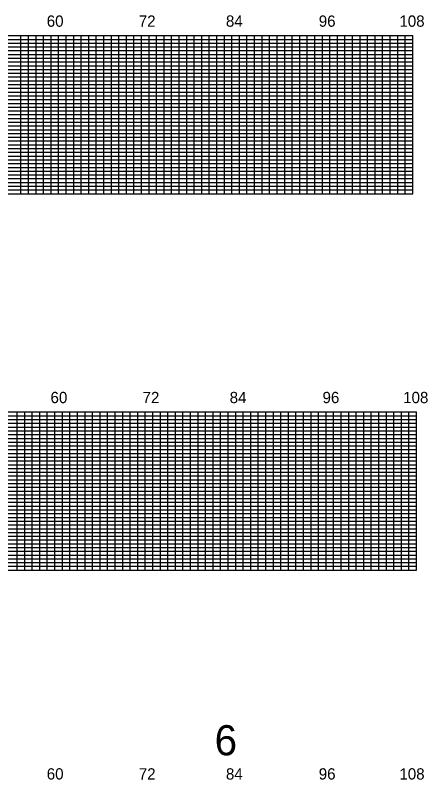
# Model space of a CAD drawing. Extents: x 1950433 to 1956806, y 750939 to 777666.
# Drawn here: x 1954069 to 1956806, y 764572 to 769649 of the extents above; entities that cross this region are included whole.
import ezdxf

# ---------------------------------------------------------------- set-up
doc = ezdxf.new("R2010")
doc.units = 0
doc.layers.add('RD_PD_WallFill', color=7, linetype='Continuous')
doc.layers.add('RD_Sketch8', color=7, linetype='Continuous')

msp = doc.modelspace()

# ---------------------------------------------------------------- linework, layer by layer
at = {"layer": 'RD_PD_WallFill'}
for p, q in [((1951356.4, 769514.1), (1956706.4, 769514.2)), ((1954106.4, 768464.2), (1954106.4, 769514.2)), ((1954156.4, 768464.2), (1954156.4, 769514.2)), ((1954206.4, 768464.2), (1954206.4, 769514.2)), ((1954256.4, 768464.2), (1954256.4, 769514.2)), ((1954306.4, 768464.2), (1954306.4, 769514.2)), ((1954356.4, 768464.2), (1954356.4, 769514.2)), ((1954406.4, 768464.2), (1954406.4, 769514.2)), ((1954456.4, 768464.1), (1954456.4, 769514.2)), ((1954506.4, 768464.2), (1954506.4, 769514.2)), ((1954556.4, 768464.2), (1954556.4, 769514.2)), ((1954606.4, 768464.2), (1954606.4, 769514.2)), ((1954656.4, 768464.2), (1954656.4, 769514.2)), ((1954706.4, 768464.2), (1954706.4, 769514.2)), ((1954756.4, 768464.1), (1954756.4, 769514.2)), ((1954806.4, 768464.1), (1954806.4, 769514.2)), ((1954856.4, 768464.2), (1954856.4, 769514.2)), ((1954906.4, 768464.2), (1954906.4, 769514.2)), ((1954956.4, 768464.2), (1954956.4, 769514.2)), ((1955006.4, 768464.2), (1955006.4, 769514.2)), ((1955056.4, 768464.2), (1955056.4, 769514.2)), ((1955106.4, 768464.2), (1955106.4, 769514.2)), ((1955156.4, 768464.2), (1955156.4, 769514.2)), ((1955206.4, 768464.2), (1955206.4, 769514.2)), ((1955256.4, 768464.2), (1955256.4, 769514.2)), ((1955306.4, 768464.2), (1955306.4, 769514.2)), ((1955356.4, 768464.2), (1955356.4, 769514.2)), ((1955406.4, 768464.2), (1955406.4, 769514.2)), ((1955456.4, 768464.2), (1955456.4, 769514.2)), ((1955506.4, 768464.2), (1955506.4, 769514.2)), ((1955556.4, 768464.2), (1955556.4, 769514.2)), ((1955606.4, 768464.2), (1955606.4, 769514.2)), ((1955656.4, 768464.2), (1955656.4, 769514.2)), ((1955706.4, 768464.2), (1955706.4, 769514.2)), ((1955756.4, 768464.2), (1955756.4, 769514.2)), ((1955806.4, 768464.2), (1955806.4, 769514.2)), ((1955856.4, 768464.2), (1955856.4, 769514.2)), ((1955906.4, 768464.2), (1955906.4, 769514.2)), ((1955956.4, 768464.2), (1955956.4, 769514.2)), ((1956006.4, 768464.2), (1956006.4, 769514.2)), ((1956056.4, 768464.2), (1956056.4, 769514.2)), ((1956106.4, 768464.2), (1956106.4, 769514.2)), ((1956156.4, 768464.2), (1956156.4, 769514.2)), ((1956206.4, 768464.2), (1956206.4, 769514.2)), ((1956256.4, 768464.2), (1956256.4, 769514.2)), ((1956306.4, 768464.2), (1956306.4, 769514.2)), ((1956356.4, 768464.2), (1956356.4, 769514.2)), ((1956406.4, 768464.2), (1956406.4, 769514.2)), ((1956456.4, 768464.2), (1956456.4, 769514.2)), ((1956506.4, 768464.2), (1956506.4, 769514.2)), ((1956556.4, 768464.2), (1956556.4, 769514.2)), ((1956606.4, 768464.2), (1956606.4, 769514.2)), ((1956656.4, 768464.2), (1956656.4, 769514.2)), ((1956706.4, 768464.2), (1956706.4, 769514.2)), ((1951806.4, 769489.1), (1956706.4, 769489.1)), ((1951806.4, 769464.1), (1956706.4, 769464.1)), ((1951806.4, 769439.1), (1956706.4, 769439.1)), ((1951806.4, 769414.2), (1956706.4, 769414.1)), ((1951356.4, 769364.1), (1956706.4, 769364.1)), ((1951806.4, 769389.1), (1956706.4, 769389.2)), ((1951356.4, 769339.1), (1956706.4, 769339.1)), ((1951356.4, 769314.1), (1956706.4, 769314.2)), ((1951356.4, 769289.2), (1956706.4, 769289.1)), ((1951356.4, 769264.2), (1956706.4, 769264.2)), ((1951356.4, 769239.1), (1956706.4, 769239.1)), ((1951356.4, 769214.1), (1956706.4, 769214.1)), ((1951356.4, 769189.2), (1956706.4, 769189.1)), ((1951356.4, 769164.1), (1956706.4, 769164.1)), ((1951356.4, 769139.2), (1956706.4, 769139.1)), ((1951356.4, 769114.1), (1956706.4, 769114.1)), ((1951356.4, 769089.1), (1956706.4, 769089.2)), ((1951356.4, 769064.1), (1956706.4, 769064.1)), ((1951356.4, 769039.1), (1956706.4, 769039.2)), ((1951356.4, 769014.1), (1956706.4, 769014.1)), ((1951356.4, 768989.1), (1956706.4, 768989.1)), ((1951356.4, 768964.2), (1956706.4, 768964.1)), ((1951356.4, 768939.1), (1956706.4, 768939.1)), ((1951356.4, 768914.1), (1956706.4, 768914.1)), ((1951356.4, 768889.1), (1956706.4, 768889.1)), ((1951356.4, 768864.1), (1956706.4, 768864.2)), ((1951356.4, 768839.1), (1956706.4, 768839.1)), ((1951356.4, 768814.1), (1956706.4, 768814.1)), ((1951356.4, 768789.1), (1956706.4, 768789.1)), ((1951356.4, 768764.1), (1956706.4, 768764.1)), ((1951356.4, 768739.1), (1956706.4, 768739.1)), ((1951356.4, 768714.1), (1956706.4, 768714.1)), ((1951356.4, 768689.1), (1956706.4, 768689.1)), ((1951356.4, 768664.1), (1956706.4, 768664.1)), ((1951356.4, 768639.1), (1956706.4, 768639.1)), ((1951356.4, 768614.1), (1956706.4, 768614.1)), ((1951356.4, 768589.1), (1956706.4, 768589.1)), ((1951356.4, 768564.1), (1956706.4, 768564.1)), ((1951356.4, 768539.1), (1956706.4, 768539.1)), ((1951356.4, 768514.1), (1956706.4, 768514.1)), ((1951406.4, 768489.1), (1956706.4, 768489.1)), ((1951356.4, 768464.1), (1956706.4, 768464.1)), ((1951381.4, 767014.1), (1956731.4, 767014.2)), ((1954081.4, 765964.2), (1954081.4, 767014.2)), ((1954131.4, 765964.2), (1954131.4, 767014.2)), ((1954181.4, 765964.2), (1954181.4, 767014.2)), ((1954231.4, 765964.2), (1954231.4, 767014.2)), ((1954281.4, 765964.2), (1954281.4, 767014.2)), ((1954331.4, 765964.2), (1954331.4, 767014.2)), ((1954381.4, 765964.2), (1954381.4, 767014.2)), ((1954431.4, 765964.2), (1954431.4, 767014.2)), ((1954481.4, 765964.1), (1954481.4, 767014.2)), ((1954531.4, 765964.2), (1954531.4, 767014.2)), ((1954581.4, 765964.2), (1954581.4, 767014.2)), ((1954631.4, 765964.2), (1954631.4, 767014.2)), ((1954681.4, 765964.2), (1954681.4, 767014.2)), ((1954731.4, 765964.2), (1954731.4, 767014.2)), ((1954781.4, 765964.1), (1954781.4, 767014.2)), ((1954831.4, 765964.1), (1954831.4, 767014.2)), ((1954881.4, 765964.2), (1954881.4, 767014.2)), ((1954931.4, 765964.2), (1954931.4, 767014.2)), ((1954981.4, 765964.2), (1954981.4, 767014.2)), ((1955031.4, 765964.2), (1955031.4, 767014.2)), ((1955081.4, 765964.2), (1955081.4, 767014.2)), ((1955131.4, 765964.2), (1955131.4, 767014.2)), ((1955181.4, 765964.2), (1955181.4, 767014.2)), ((1955231.4, 765964.2), (1955231.4, 767014.2)), ((1955281.4, 765964.2), (1955281.4, 767014.2)), ((1955331.4, 765964.2), (1955331.4, 767014.2)), ((1955381.4, 765964.2), (1955381.4, 767014.2)), ((1955431.4, 765964.2), (1955431.4, 767014.2)), ((1955481.4, 765964.2), (1955481.4, 767014.2)), ((1955531.4, 765964.2), (1955531.4, 767014.2)), ((1955581.4, 765964.2), (1955581.4, 767014.2)), ((1955631.4, 765964.2), (1955631.4, 767014.2)), ((1955681.4, 765964.2), (1955681.4, 767014.2)), ((1955731.4, 765964.2), (1955731.4, 767014.2)), ((1955781.4, 765964.2), (1955781.4, 767014.2)), ((1955831.4, 765964.2), (1955831.4, 767014.2)), ((1955881.4, 765964.2), (1955881.4, 767014.2)), ((1955931.4, 765964.2), (1955931.4, 767014.2)), ((1955981.4, 765964.2), (1955981.4, 767014.2)), ((1956031.4, 765964.2), (1956031.4, 767014.2)), ((1956081.4, 765964.2), (1956081.4, 767014.2)), ((1956131.4, 765964.2), (1956131.4, 767014.2)), ((1956181.4, 765964.2), (1956181.4, 767014.2)), ((1956231.4, 765964.2), (1956231.4, 767014.2)), ((1956281.4, 765964.2), (1956281.4, 767014.2)), ((1956331.4, 765964.2), (1956331.4, 767014.2)), ((1956381.4, 765964.2), (1956381.4, 767014.2)), ((1956431.4, 765964.2), (1956431.4, 767014.2)), ((1956481.4, 765964.2), (1956481.4, 767014.2)), ((1956531.4, 765964.2), (1956531.4, 767014.2)), ((1956581.4, 765964.2), (1956581.4, 767014.2)), ((1956631.4, 765964.2), (1956631.4, 767014.2)), ((1956681.4, 765964.2), (1956681.4, 767014.2)), ((1956731.4, 765964.2), (1956731.4, 767014.2)), ((1951831.4, 766989.1), (1956731.4, 766989.1)), ((1951831.4, 766964.1), (1956731.4, 766964.1)), ((1951831.4, 766939.1), (1956731.4, 766939.1)), ((1951831.4, 766914.2), (1956731.4, 766914.1)), ((1951381.4, 766864.1), (1956731.4, 766864.1)), ((1951831.4, 766889.1), (1956731.4, 766889.2)), ((1951381.4, 766839.1), (1956731.4, 766839.1)), ((1951381.4, 766814.1), (1956731.4, 766814.2)), ((1951381.4, 766789.2), (1956731.4, 766789.1)), ((1951381.4, 766764.2), (1956731.4, 766764.2)), ((1951381.4, 766739.1), (1956731.4, 766739.1)), ((1951381.4, 766714.1), (1956731.4, 766714.1)), ((1951381.4, 766689.2), (1956731.4, 766689.1)), ((1951381.4, 766664.1), (1956731.4, 766664.1)), ((1951381.4, 766639.2), (1956731.4, 766639.1)), ((1951381.4, 766614.1), (1956731.4, 766614.1)), ((1951381.4, 766589.1), (1956731.4, 766589.2)), ((1951381.4, 766564.1), (1956731.4, 766564.1)), ((1951381.4, 766539.1), (1956731.4, 766539.2)), ((1951381.4, 766514.1), (1956731.4, 766514.1)), ((1951381.4, 766489.1), (1956731.4, 766489.1)), ((1951381.4, 766464.2), (1956731.4, 766464.1)), ((1951381.4, 766439.1), (1956731.4, 766439.1)), ((1951381.4, 766414.1), (1956731.4, 766414.1)), ((1951381.4, 766389.1), (1956731.4, 766389.1)), ((1951381.4, 766364.1), (1956731.4, 766364.2)), ((1951381.4, 766339.1), (1956731.4, 766339.1)), ((1951381.4, 766314.1), (1956731.4, 766314.1)), ((1951381.4, 766289.1), (1956731.4, 766289.1)), ((1951381.4, 766264.1), (1956731.4, 766264.1)), ((1951381.4, 766239.1), (1956731.4, 766239.1)), ((1951381.4, 766214.1), (1956731.4, 766214.1)), ((1951381.4, 766189.1), (1956731.4, 766189.1)), ((1951381.4, 766164.1), (1956731.4, 766164.1)), ((1951381.4, 766139.1), (1956731.4, 766139.1)), ((1951381.4, 766114.1), (1956731.4, 766114.1)), ((1951381.4, 766089.1), (1956731.4, 766089.1)), ((1951381.4, 766064.1), (1956731.4, 766064.1)), ((1951381.4, 766039.1), (1956731.4, 766039.1)), ((1951381.4, 766014.1), (1956731.4, 766014.1)), ((1951381.4, 765964.1), (1956731.4, 765964.1)), ((1951431.4, 765989.1), (1956731.4, 765989.1))]:
    msp.add_line(p, q, dxfattribs=at)

# ---------------------------------------------------------------- texts
for s, p in [('60', (1954277.5, 769572.8)), ('72', (1954888.2, 769572.8)), ('84', (1955466.5, 769572.8)), ('96', (1956082.5, 769572.8)), ('108', (1956617.6, 769572.8)), ('60', (1954302.5, 767072.8)), ('72', (1954913.2, 767072.8)), ('84', (1955491.5, 767072.8)), ('96', (1956107.5, 767072.8)), ('108', (1956642.6, 767072.8)), ('60', (1954277.5, 764572.8)), ('72', (1954888.2, 764572.8)), ('84', (1955466.5, 764572.8)), ('96', (1956082.5, 764572.8)), ('108', (1956617.6, 764572.8))]:
    msp.add_text(s, height=75, dxfattribs=at).set_placement(p)
at = {"layer": 'RD_Sketch8'}
msp.add_text('6', height=200, dxfattribs=at).set_placement((1955391.7, 764733.9))

doc.saveas('drawing.dxf')
